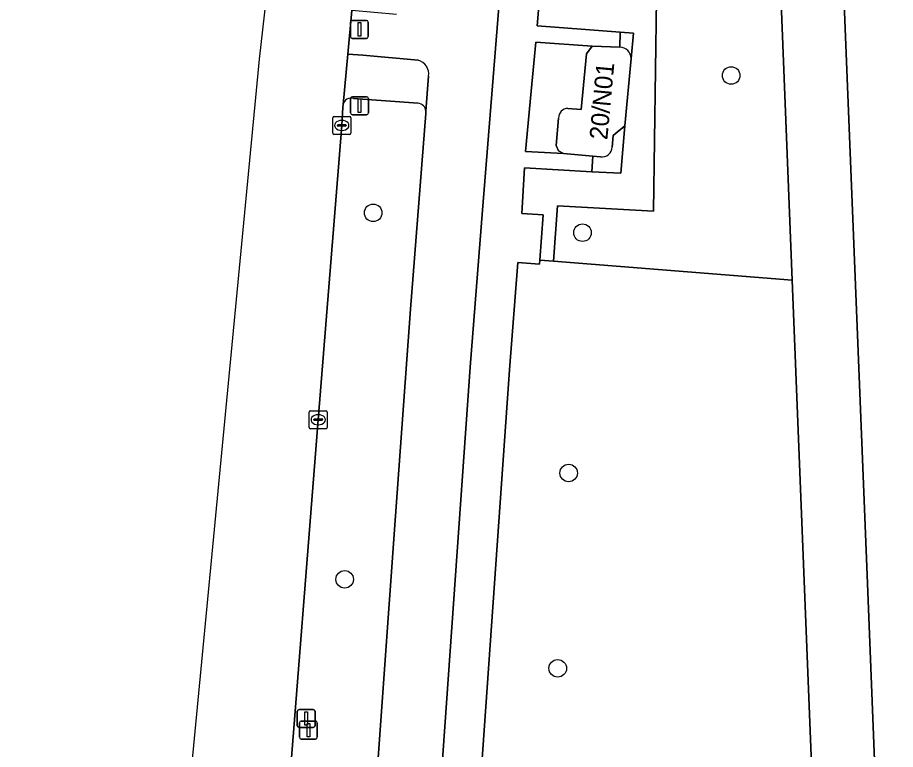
# Model space of a CAD drawing. Extents: x 161241 to 161758, y 384138 to 384885.
# Drawn here: x 161241.27 to 161290.12, y 384240.3 to 384281.06 of the extents above; entities that cross this region are included whole.
import ezdxf

# ---------------------------------------------------------------- set-up
doc = ezdxf.new("R2010")
doc.units = 0
for name, color, linetype in [('IMGEO_Berm_groen', 7, 'Continuous'), ('IMGEO_Boom', 7, 'Continuous'), ('IMGEO_Erf', 7, 'Continuous'), ('IMGEO_Fietspad_gesloten', 7, 'Continuous'), ('IMGEO_Groenvoorziening', 7, 'Continuous'), ('IMGEO_Kolk', 7, 'Continuous'), ('IMGEO_Lichtmast', 7, 'Continuous'), ('IMGEO_OVBaan_gesloten', 7, 'Continuous'), ('IMGEO_Pand', 7, 'Continuous'), ('IMGEO_Pand_nummerreeks', 7, 'Continuous'), ('IMGEO_Voetpad_open', 7, 'Continuous')]:
    doc.layers.add(name, color=color, linetype=linetype)

msp = doc.modelspace()

# ---------------------------------------------------------------- linework, layer by layer
at = {"layer": 'IMGEO_Berm_groen'}
for points in [[(161263.559, 384276.285), (161259.964, 384276.56)], [(161259.381, 384276.22), (161259.367, 384276.07), (161259.312, 384275.054), (161258.002, 384258.664), (161256.24, 384236.299), (161254.778, 384217.347), (161253.117, 384195.97), (161251.591, 384176.567), (161251.316, 384173.143), (161250.106, 384158.053), (161249.949, 384156.206), (161249.934, 384156.079), (161249.919, 384155.257)], [(161252.937, 384155.312), (161253.797, 384163.617), (161254.402, 384168.209), (161255.111, 384172.583), (161255.727, 384175.693), (161256.945, 384180.975), (161257.099, 384182.165), (161257.318, 384184.907), (161259.279, 384210.879), (161261.604, 384243.474), (161262.305, 384253.304), (161262.927, 384262.016), (161263.143, 384264.813), (161263.983, 384275.709), (161263.994, 384275.849)]]:
    msp.add_lwpolyline(points, dxfattribs=at)
for centre, start, end in [((161259.839, 384276.105), 74.5686, 165.9321), ((161263.523, 384275.814), 4.2301, 85.6384)]:
    msp.add_arc(centre, 0.472, start, end, dxfattribs=at)
at = {"layer": 'IMGEO_Boom'}
for centre in [(161280.983, 384277.833), (161261.061, 384270.183), (161272.71, 384269.077), (161271.937, 384255.694), (161259.472, 384249.773), (161271.331, 384244.819)]:
    msp.add_circle(centre, 0.489, dxfattribs=at)
at = {"layer": 'IMGEO_Erf'}
msp.add_lwpolyline([(161286.795, 384293.851), (161288.542, 384250), (161289.176, 384234.089)], dxfattribs=at)
at = {"layer": 'IMGEO_Fietspad_gesloten'}
for points in [[(161258.742, 384157.135), (161260.876, 384184.71), (161262.854, 384210.484), (161266.448, 384261.586), (161267.146, 384270.325), (161268.291, 384284.663), (161268.569, 384287.683), (161268.583, 384287.814), (161270.005, 384301.578), (161270.134, 384303.063), (161273.019, 384327.449), (161276.269, 384355.259), (161281.811, 384402.692), (161289.671, 384470.352), (161296.755, 384531.182), (161299.82, 384554.106), (161304.483, 384590.763), (161310.58, 384642.356), (161311.044, 384646.284), (161311.712, 384651.942), (161311.774, 384652.424)], [(161262.361, 384281.225), (161259.867, 384281.454), (161259.641, 384279.02), (161260.484, 384278.968), (161263.557, 384278.689)], [(161264.144, 384277.795), (161263.994, 384275.849), (161263.983, 384275.709), (161263.143, 384264.813), (161262.927, 384262.016), (161262.305, 384253.304), (161261.604, 384243.474), (161259.279, 384210.879), (161257.318, 384184.907), (161257.099, 384182.165), (161256.945, 384180.975), (161255.727, 384175.693), (161255.111, 384172.583), (161254.402, 384168.209), (161253.797, 384163.617), (161252.937, 384155.312), (161252.667, 384152.165), (161249.515, 384152.442), (161249.36, 384150.604), (161249.247, 384149.144), (161249.868, 384149.175), (161249.943, 384149.179), (161251.751, 384149.281), (161251.938, 384149.291)]]:
    msp.add_lwpolyline(points, dxfattribs=at)
msp.add_arc((161263.347, 384277.911), 0.806, 351.7138, 74.8639, dxfattribs=at)
at = {"layer": 'IMGEO_Groenvoorziening'}
for points in [[(161272.888, 384197.971), (161274.519, 384199.728), (161287.535, 384200.127), (161286.463, 384228.528), (161289.176, 384234.089), (161288.542, 384250), (161286.795, 384293.851), (161291.319, 384298.89), (161300.109, 384299.408)], [(161284.385, 384266.432), (161283.264, 384294.561)], [(161283.264, 384294.561), (161284.385, 384266.432)], [(161276.141, 384292.581), (161270.995, 384290.346), (161270.194, 384280.594), (161272.878, 384280.394), (161274.803, 384280.25), (161275.543, 384280.195), (161275.415, 384278.786), (161275.073, 384275.029), (161274.833, 384272.389), (161273.226, 384272.477), (161269.486, 384272.682), (161269.327, 384270.147), (161270.525, 384270.075), (161270.33, 384267.547), (161271.096, 384267.486), (161271.311, 384270.579), (161276.661, 384270.286), (161276.83, 384282.104), (161273.116, 384282.399), (161274.077, 384289.358), (161278.317, 384291.304)], [(161278.317, 384291.304), (161274.077, 384289.358), (161273.116, 384282.399), (161276.83, 384282.104), (161276.661, 384270.286), (161271.311, 384270.579), (161271.096, 384267.486)], [(161275.415, 384278.786), (161275.543, 384280.195), (161274.803, 384280.25), (161274.791, 384279.413)], [(161272.923, 384279.031), (161273.24, 384279.465), (161270.111, 384279.698), (161269.854, 384276.964), (161269.538, 384273.591), (161271.652, 384273.491), (161271.373, 384273.645), (161271.234, 384273.931), (161271.375, 384275.46)], [(161271.895, 384275.997), (161272.641, 384275.93), (161272.923, 384279.031)], [(161273.707, 384273.311), (161273.291, 384273.347), (161273.226, 384272.477), (161274.833, 384272.389), (161275.073, 384275.029), (161274.424, 384274.489), (161274.366, 384273.847)], [(161271.096, 384267.486), (161284.385, 384266.432)], [(161284.385, 384266.432), (161285.644, 384234.831), (161282.932, 384229.273), (161283.905, 384203.517), (161272.718, 384203.175)]]:
    msp.add_lwpolyline(points, dxfattribs=at)
msp.add_lwpolyline([(161284.385, 384266.432), (161271.096, 384267.486), (161270.33, 384267.547), (161270.314, 384267.335), (161269.116, 384267.426), (161268.653, 384261.442), (161265.049, 384210.182), (161264.495, 384202.929), (161265.239, 384202.946), (161268.25, 384203.038), (161272.718, 384203.175), (161283.905, 384203.517), (161282.932, 384229.273), (161285.644, 384234.831)], close=True, dxfattribs=at)
for centre, radius, start, end in [((161274.761, 384278.759), 0.654, 2.3218, 87.4034), ((161271.894, 384275.478), 0.519, 89.8914, 181.9514), ((161273.793, 384273.878), 0.574, 261.363, 356.8836)]:
    msp.add_arc(centre, radius, start, end, dxfattribs=at)
at = {"layer": 'IMGEO_Kolk'}
for p, q in [((161258.811, 384274.628), (161258.811, 384275.48)), ((161258.886, 384275.554), (161259.738, 384275.554)), ((161259.812, 384275.48), (161259.812, 384274.628)), ((161259.07, 384275.048), (161259.07, 384275.06)), ((161259.508, 384275.011), (161259.11, 384275.011)), ((161259.113, 384275.097), (161259.511, 384275.097)), ((161259.299, 384275.334), (161259.324, 384275.334)), ((161259.554, 384275.06), (161259.554, 384275.048)), ((161259.738, 384274.554), (161258.886, 384274.554)), ((161259.322, 384274.774), (161259.297, 384274.774)), ((161257.501, 384258.238), (161257.501, 384259.09)), ((161257.576, 384259.164), (161258.428, 384259.164)), ((161257.989, 384258.944), (161258.014, 384258.944)), ((161258.502, 384259.09), (161258.502, 384258.238)), ((161257.76, 384258.658), (161257.76, 384258.67)), ((161258.198, 384258.621), (161257.8, 384258.621)), ((161257.803, 384258.707), (161258.201, 384258.707)), ((161258.012, 384258.384), (161257.987, 384258.384)), ((161258.244, 384258.67), (161258.244, 384258.658)), ((161258.428, 384258.164), (161257.576, 384258.164))]:
    msp.add_line(p, q, dxfattribs=at)
for points in [[(161258.811, 384274.628), (161258.811, 384275.48)], [(161258.886, 384275.554), (161259.738, 384275.554)], [(161259.812, 384275.48), (161259.812, 384274.628)], [(161259.738, 384274.554), (161258.886, 384274.554)], [(161257.501, 384258.238), (161257.501, 384259.09)], [(161257.576, 384259.164), (161258.428, 384259.164)], [(161258.502, 384259.09), (161258.502, 384258.238)], [(161258.428, 384258.164), (161257.576, 384258.164)]]:
    msp.add_lwpolyline(points, dxfattribs=at)
for centre, radius, start, end in [((161258.888, 384275.478), 0.0765, 91.552, 178.448), ((161258.888, 384275.478), 0.0765, 91.552, 178.448), ((161259.736, 384275.478), 0.0765, 1.552, 88.448), ((161259.736, 384275.478), 0.0765, 1.552, 88.448), ((161259.11, 384275.057), 0.0403, 85.8775, 175.7526), ((161259.107, 384275.047), 0.0366, 178.938, 274.7102), ((161259.511, 384275.054), 0.043, 264.8664, 352.4533), ((161259.515, 384275.059), 0.0386, 1.7309, 96.639), ((161258.888, 384274.63), 0.0765, 181.552, 268.448), ((161258.888, 384274.63), 0.0765, 181.552, 268.448), ((161259.736, 384274.63), 0.0765, 271.552, 358.448), ((161259.736, 384274.63), 0.0765, 271.552, 358.448), ((161257.578, 384259.088), 0.0765, 91.552, 178.448), ((161257.578, 384259.088), 0.0765, 91.552, 178.448), ((161258.426, 384259.088), 0.0765, 1.552, 88.448), ((161258.426, 384259.088), 0.0765, 1.552, 88.448), ((161257.8, 384258.667), 0.0403, 85.8775, 175.7526), ((161257.797, 384258.657), 0.0366, 178.938, 274.7102), ((161258.201, 384258.664), 0.043, 264.8664, 352.4533), ((161258.205, 384258.669), 0.0386, 1.7309, 96.639), ((161257.578, 384258.24), 0.0765, 181.552, 268.448), ((161257.578, 384258.24), 0.0765, 181.552, 268.448), ((161258.426, 384258.24), 0.0765, 271.552, 358.448), ((161258.426, 384258.24), 0.0765, 271.552, 358.448)]:
    msp.add_arc(centre, radius, start, end, dxfattribs=at)
for centre, major_axis, ratio, start_param, end_param in [((161259.298, 384275.054), (-0.387, 0.002), 0.722429, 4.712389, 7.853982), ((161259.323, 384275.054), (-0.39, 0.002), 0.717154, 1.570796, 4.712389), ((161257.988, 384258.664), (-0.387, 0.002), 0.722429, 4.712389, 7.853982), ((161258.013, 384258.664), (-0.39, 0.002), 0.717154, 1.570796, 4.712389)]:
    msp.add_ellipse(centre, major_axis=major_axis, ratio=ratio, start_param=start_param, end_param=end_param, dxfattribs=at)
at = {"layer": 'IMGEO_Lichtmast'}
for p, q in [((161259.795, 384280), (161259.795, 384280.8)), ((161259.795, 384280.8), (161259.795, 384280)), ((161259.895, 384280.9), (161260.685, 384280.9)), ((161260.685, 384280.9), (161259.895, 384280.9)), ((161260.785, 384280.8), (161260.785, 384280)), ((161260.785, 384280), (161260.785, 384280.8)), ((161260.685, 384279.9), (161259.895, 384279.9)), ((161259.895, 384279.9), (161260.685, 384279.9)), ((161259.804, 384275.75), (161259.804, 384276.55)), ((161259.804, 384276.55), (161259.804, 384275.75)), ((161259.904, 384276.65), (161260.694, 384276.65)), ((161260.694, 384276.65), (161259.904, 384276.65)), ((161260.794, 384276.55), (161260.794, 384275.75)), ((161260.794, 384275.75), (161260.794, 384276.55)), ((161260.694, 384275.65), (161259.904, 384275.65)), ((161259.904, 384275.65), (161260.694, 384275.65)), ((161256.838, 384241.625), (161256.838, 384242.425)), ((161256.838, 384242.425), (161256.838, 384241.625)), ((161256.938, 384242.525), (161257.728, 384242.525)), ((161257.728, 384242.525), (161256.938, 384242.525)), ((161257.828, 384242.425), (161257.828, 384241.625)), ((161257.828, 384241.625), (161257.828, 384242.425)), ((161256.957, 384240.979), (161256.957, 384241.779)), ((161256.957, 384241.779), (161256.957, 384240.979)), ((161257.057, 384241.879), (161257.847, 384241.879)), ((161257.847, 384241.879), (161257.057, 384241.879)), ((161257.947, 384241.779), (161257.947, 384240.979)), ((161257.947, 384240.979), (161257.947, 384241.779)), ((161257.728, 384241.525), (161256.938, 384241.525)), ((161256.938, 384241.525), (161257.728, 384241.525)), ((161257.847, 384240.879), (161257.057, 384240.879)), ((161257.057, 384240.879), (161257.847, 384240.879))]:
    msp.add_line(p, q, dxfattribs=at)
for points in [[(161260.215, 384280.775), (161260.365, 384280.775), (161260.365, 384280.025), (161260.215, 384280.025), (161260.215, 384280.775)], [(161260.224, 384276.525), (161260.374, 384276.525), (161260.374, 384275.775), (161260.224, 384275.775), (161260.224, 384276.525)], [(161257.258, 384242.4), (161257.408, 384242.4), (161257.408, 384241.65), (161257.258, 384241.65), (161257.258, 384242.4)], [(161257.377, 384241.754), (161257.527, 384241.754), (161257.527, 384241.004), (161257.377, 384241.004), (161257.377, 384241.754)]]:
    msp.add_lwpolyline(points, dxfattribs=at)
for centre, start, end in [((161259.895, 384280.8), 90, 180), ((161259.895, 384280.8), 90, 180), ((161260.685, 384280.8), 0, 90), ((161260.685, 384280.8), 360, 90), ((161259.895, 384280), 180, 270), ((161259.895, 384280), 180, 270), ((161260.685, 384280), 270, 0), ((161260.685, 384280), 270, 0), ((161259.904, 384276.55), 90, 180), ((161259.904, 384276.55), 90, 180), ((161260.694, 384276.55), 0, 90), ((161260.694, 384276.55), 360, 90), ((161259.904, 384275.75), 180, 270), ((161259.904, 384275.75), 180, 270), ((161260.694, 384275.75), 270, 0), ((161260.694, 384275.75), 270, 0), ((161256.938, 384242.425), 90, 180), ((161256.938, 384242.425), 90, 180), ((161257.728, 384242.425), 0, 90), ((161257.728, 384242.425), 360, 90), ((161257.057, 384241.779), 90, 180), ((161257.057, 384241.779), 90, 180), ((161257.847, 384241.779), 0, 90), ((161257.847, 384241.779), 360, 90), ((161256.938, 384241.625), 180, 270), ((161256.938, 384241.625), 180, 270), ((161257.728, 384241.625), 270, 0), ((161257.728, 384241.625), 270, 0), ((161257.057, 384240.979), 180, 270), ((161257.057, 384240.979), 180, 270), ((161257.847, 384240.979), 270, 0), ((161257.847, 384240.979), 270, 0)]:
    msp.add_arc(centre, 0.1, start, end, dxfattribs=at)
at = {"layer": 'IMGEO_OVBaan_gesloten'}
for points in [[(161312.353, 384812.006), (161309.921, 384834.117), (161309.774, 384835.487), (161309.446, 384838.541), (161309.033, 384842.394), (161308.618, 384846.264), (161308.42, 384848.049), (161305.427, 384848.093), (161310.221, 384805.365), (161309.046, 384772.256), (161307.924, 384740.658), (161299.466, 384666.717), (161288.788, 384573.374), (161256.675, 384295.749), (161254.709, 384278.75), (161244.663, 384173.474), (161243.814, 384162.675), (161243.598, 384159.911), (161243.455, 384158.862), (161242.942, 384154.711), (161242.923, 384154.593), (161242.753, 384153.458), (161241.269, 384137.91)], [(161256.24, 384236.299), (161258.002, 384258.664), (161259.312, 384275.054), (161259.367, 384276.07), (161259.381, 384276.22), (161259.641, 384279.02), (161259.867, 384281.454), (161259.915, 384281.975), (161259.918, 384282.004), (161260.014, 384283.129), (161261.613, 384299.182), (161261.706, 384299.932)]]:
    msp.add_lwpolyline(points, dxfattribs=at)
at = {"layer": 'IMGEO_Pand'}
for points in [[(161274.791, 384279.413), (161273.24, 384279.465), (161272.923, 384279.031), (161272.641, 384275.93), (161271.895, 384275.997)], [(161274.366, 384273.847), (161274.424, 384274.489), (161275.073, 384275.029), (161275.415, 384278.786)], [(161271.375, 384275.46), (161271.234, 384273.931), (161271.373, 384273.645), (161271.652, 384273.491), (161273.291, 384273.347), (161273.707, 384273.311)]]:
    msp.add_lwpolyline(points, dxfattribs=at)
for centre, radius, start, end in [((161274.761, 384278.759), 0.654, 2.3218, 87.4034), ((161271.894, 384275.478), 0.519, 89.8914, 181.9514), ((161273.793, 384273.878), 0.574, 261.363, 356.8836)]:
    msp.add_arc(centre, radius, start, end, dxfattribs=at)
at = {"layer": 'IMGEO_Voetpad_open'}
for points in [[(161268.653, 384261.442), (161269.116, 384267.426), (161270.314, 384267.335), (161270.33, 384267.547), (161270.525, 384270.075), (161269.327, 384270.147), (161269.486, 384272.682), (161273.226, 384272.477), (161273.291, 384273.347), (161271.652, 384273.491), (161269.538, 384273.591), (161269.854, 384276.964), (161270.111, 384279.698), (161273.24, 384279.465), (161274.791, 384279.413), (161274.803, 384280.25), (161272.878, 384280.394), (161270.194, 384280.594), (161270.995, 384290.346), (161270.3, 384290.045)], [(161268.583, 384287.814), (161268.569, 384287.683), (161268.291, 384284.663), (161267.146, 384270.325), (161266.448, 384261.586), (161262.854, 384210.484), (161260.876, 384184.71), (161258.742, 384157.135)], [(161260.484, 384278.968), (161259.641, 384279.02), (161259.381, 384276.22)], [(161263.557, 384278.689), (161260.484, 384278.968)], [(161263.994, 384275.849), (161264.144, 384277.795)], [(161259.964, 384276.56), (161263.559, 384276.285)], [(161261.07, 384158.294), (161263.087, 384184.499), (161264.495, 384202.929), (161265.049, 384210.182), (161268.653, 384261.442)]]:
    msp.add_lwpolyline(points, dxfattribs=at)
for centre, radius, start, end in [((161263.347, 384277.911), 0.806, 351.7138, 74.8639), ((161259.839, 384276.105), 0.472, 74.5686, 165.9321), ((161263.523, 384275.814), 0.472, 4.2301, 85.6384)]:
    msp.add_arc(centre, radius, start, end, dxfattribs=at)

# ---------------------------------------------------------------- texts
at = {"layer": 'IMGEO_Pand_nummerreeks'}
msp.add_text('20/N01', height=1, rotation=84.7331, dxfattribs=at).set_placement((161274.088, 384274.221))

doc.saveas('drawing.dxf')
